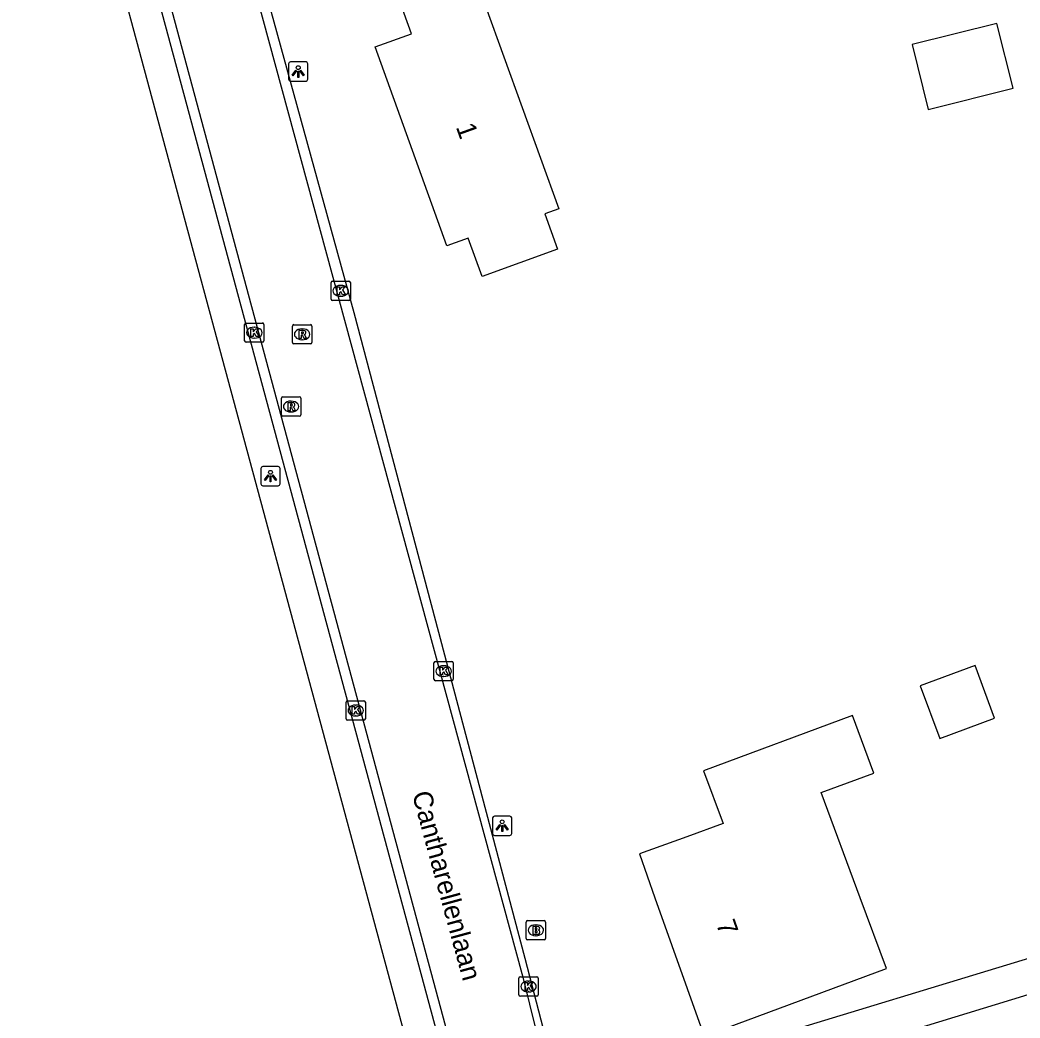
# Model space of a CAD drawing. Extents: x 162675 to 163482, y 379761 to 381227.
# Drawn here: x 162822.9 to 162874.7, y 380743.8 to 380795.5 of the extents above; entities that cross this region are included whole.
import ezdxf

# ---------------------------------------------------------------- set-up
doc = ezdxf.new("R2010")
doc.units = 0
for name, color, linetype in [('IMGEO_Brandkraan', 7, 'Continuous'), ('IMGEO_Kolk', 7, 'Continuous'), ('IMGEO_Lichtpunt', 7, 'Continuous'), ('IMGEO_Openbare_ruimte_label', 7, 'Continuous'), ('IMGEO_Pand', 7, 'Continuous'), ('IMGEO_Pand_nummerreeks', 7, 'Continuous'), ('IMGEO_Rijbaan_lokaal_gesloten', 7, 'Continuous'), ('IMGEO_Rijbaan_lokaal_open', 7, 'Continuous'), ('IMGEO_Rioolput', 7, 'Continuous'), ('IMGEO_Voetpad_open', 7, 'Continuous')]:
    doc.layers.add(name, color=color, linetype=linetype)

msp = doc.modelspace()

# ---------------------------------------------------------------- linework, layer by layer
at = {"layer": 'IMGEO_Brandkraan'}
for p, q in [((162849.144, 380747.89), (162849.144, 380748.742)), ((162849.219, 380748.816), (162850.071, 380748.816)), ((162850.145, 380748.742), (162850.145, 380747.89)), ((162849.632, 380748.596), (162849.657, 380748.596)), ((162850.071, 380747.816), (162849.219, 380747.816)), ((162849.655, 380748.036), (162849.63, 380748.036))]:
    msp.add_line(p, q, dxfattribs=at)
for points in [[(162849.144, 380747.89), (162849.144, 380748.742)], [(162849.219, 380748.816), (162850.071, 380748.816)], [(162850.145, 380748.742), (162850.145, 380747.89)], [(162849.492, 380748.516), (162849.492, 380748.116), (162849.705, 380748.116)], [(162849.723, 380748.516), (162849.492, 380748.516)], [(162849.671, 380748.435), (162849.617, 380748.435), (162849.617, 380748.359)], [(162849.617, 380748.359), (162849.67, 380748.359)], [(162849.679, 380748.283), (162849.617, 380748.283), (162849.617, 380748.202)], [(162850.071, 380747.816), (162849.219, 380747.816)], [(162849.617, 380748.202), (162849.679, 380748.202)]]:
    msp.add_lwpolyline(points, dxfattribs=at)
for centre, radius, start, end in [((162849.221, 380748.74), 0.0765, 91.552, 178.448), ((162849.221, 380748.74), 0.0765, 91.552, 178.448), ((162850.069, 380748.74), 0.0765, 1.552, 88.448), ((162850.069, 380748.74), 0.0765, 1.552, 88.448), ((162849.672, 380748.397), 0.0379, 267.8285, 90.9355), ((162849.68, 380748.242), 0.0404, 269.8759, 90.5077), ((162849.727, 380748.371), 0.145, 59.4692, 91.5367), ((162849.752, 380748.418), 0.0922, 285.5137, 58.1501), ((162849.757, 380748.226), 0.105, 301.3115, 78.989), ((162849.221, 380747.892), 0.0765, 181.552, 268.448), ((162849.221, 380747.892), 0.0765, 181.552, 268.448), ((162849.711, 380748.367), 0.251, 268.6676, 293.5347), ((162850.069, 380747.892), 0.0765, 271.552, 358.448), ((162850.069, 380747.892), 0.0765, 271.552, 358.448)]:
    msp.add_arc(centre, radius, start, end, dxfattribs=at)
for centre, major_axis, ratio, start_param, end_param in [((162849.631, 380748.316), (-0.387, 0.002), 0.722429, 4.712389, 7.853982), ((162849.656, 380748.316), (-0.39, 0.002), 0.717154, 1.570796, 4.712389)]:
    msp.add_ellipse(centre, major_axis=major_axis, ratio=ratio, start_param=start_param, end_param=end_param, dxfattribs=at)
at = {"layer": 'IMGEO_Kolk'}
for p, q in [((162839.111, 380781.945), (162839.963, 380781.945)), ((162839.036, 380781.019), (162839.036, 380781.871)), ((162839.524, 380781.725), (162839.549, 380781.725)), ((162840.037, 380781.871), (162840.037, 380781.019)), ((162839.963, 380780.945), (162839.111, 380780.945)), ((162839.547, 380781.165), (162839.522, 380781.165)), ((162834.56, 380778.851), (162834.56, 380779.703)), ((162834.635, 380779.777), (162835.487, 380779.777)), ((162835.048, 380779.557), (162835.073, 380779.557)), ((162835.561, 380779.703), (162835.561, 380778.851)), ((162835.071, 380778.997), (162835.046, 380778.997)), ((162835.487, 380778.777), (162834.635, 380778.777)), ((162844.442, 380762.244), (162845.294, 380762.244)), ((162844.367, 380761.318), (162844.367, 380762.17)), ((162844.855, 380762.024), (162844.88, 380762.024)), ((162845.368, 380762.17), (162845.368, 380761.318)), ((162845.294, 380761.244), (162844.442, 380761.244)), ((162844.878, 380761.464), (162844.853, 380761.464)), ((162839.891, 380760.204), (162840.743, 380760.204)), ((162839.816, 380759.278), (162839.816, 380760.13)), ((162840.304, 380759.984), (162840.329, 380759.984)), ((162840.817, 380760.13), (162840.817, 380759.278)), ((162840.743, 380759.204), (162839.891, 380759.204)), ((162840.327, 380759.424), (162840.302, 380759.424)), ((162848.767, 380744.978), (162848.767, 380745.83)), ((162848.842, 380745.904), (162849.694, 380745.904)), ((162849.255, 380745.684), (162849.28, 380745.684)), ((162849.768, 380745.83), (162849.768, 380744.978)), ((162849.278, 380745.124), (162849.253, 380745.124)), ((162849.694, 380744.904), (162848.842, 380744.904))]:
    msp.add_line(p, q, dxfattribs=at)
for points in [[(162839.111, 380781.945), (162839.963, 380781.945)], [(162839.036, 380781.019), (162839.036, 380781.871)], [(162839.357, 380781.645), (162839.48, 380781.645), (162839.48, 380781.494), (162839.61, 380781.645), (162839.774, 380781.645), (162839.628, 380781.494), (162839.781, 380781.245), (162839.629, 380781.245), (162839.544, 380781.409), (162839.48, 380781.342), (162839.48, 380781.245), (162839.357, 380781.245), (162839.357, 380781.645)], [(162840.037, 380781.871), (162840.037, 380781.019)], [(162839.963, 380780.945), (162839.111, 380780.945)], [(162834.56, 380778.851), (162834.56, 380779.703)], [(162834.635, 380779.777), (162835.487, 380779.777)], [(162834.881, 380779.477), (162835.004, 380779.477), (162835.004, 380779.326), (162835.134, 380779.477), (162835.298, 380779.477), (162835.152, 380779.326), (162835.305, 380779.077), (162835.153, 380779.077), (162835.068, 380779.241), (162835.004, 380779.174), (162835.004, 380779.077), (162834.881, 380779.077), (162834.881, 380779.477)], [(162835.561, 380779.703), (162835.561, 380778.851)], [(162835.487, 380778.777), (162834.635, 380778.777)], [(162844.442, 380762.244), (162845.294, 380762.244)], [(162844.367, 380761.318), (162844.367, 380762.17)], [(162844.688, 380761.944), (162844.811, 380761.944), (162844.811, 380761.793), (162844.941, 380761.944), (162845.105, 380761.944), (162844.959, 380761.793), (162845.112, 380761.544), (162844.96, 380761.544), (162844.875, 380761.708), (162844.811, 380761.641), (162844.811, 380761.544), (162844.688, 380761.544), (162844.688, 380761.944)], [(162845.368, 380762.17), (162845.368, 380761.318)], [(162845.294, 380761.244), (162844.442, 380761.244)], [(162839.891, 380760.204), (162840.743, 380760.204)], [(162839.816, 380759.278), (162839.816, 380760.13)], [(162840.137, 380759.904), (162840.26, 380759.904), (162840.26, 380759.753), (162840.39, 380759.904), (162840.554, 380759.904), (162840.408, 380759.753), (162840.561, 380759.504), (162840.409, 380759.504), (162840.324, 380759.668), (162840.26, 380759.601), (162840.26, 380759.504), (162840.137, 380759.504), (162840.137, 380759.904)], [(162840.817, 380760.13), (162840.817, 380759.278)], [(162840.743, 380759.204), (162839.891, 380759.204)], [(162848.767, 380744.978), (162848.767, 380745.83)], [(162848.842, 380745.904), (162849.694, 380745.904)], [(162849.768, 380745.83), (162849.768, 380744.978)], [(162849.088, 380745.604), (162849.211, 380745.604), (162849.211, 380745.453), (162849.341, 380745.604), (162849.505, 380745.604), (162849.359, 380745.453), (162849.512, 380745.204), (162849.36, 380745.204), (162849.275, 380745.368), (162849.211, 380745.301), (162849.211, 380745.204), (162849.088, 380745.204), (162849.088, 380745.604)], [(162849.694, 380744.904), (162848.842, 380744.904)]]:
    msp.add_lwpolyline(points, dxfattribs=at)
for centre, start, end in [((162839.113, 380781.869), 91.552, 178.448), ((162839.113, 380781.869), 91.552, 178.448), ((162839.961, 380781.869), 1.552, 88.448), ((162839.961, 380781.869), 1.552, 88.448), ((162839.113, 380781.021), 181.552, 268.448), ((162839.113, 380781.021), 181.552, 268.448), ((162839.961, 380781.021), 271.552, 358.448), ((162839.961, 380781.021), 271.552, 358.448), ((162834.637, 380779.701), 91.552, 178.448), ((162834.637, 380779.701), 91.552, 178.448), ((162835.485, 380779.701), 1.552, 88.448), ((162835.485, 380779.701), 1.552, 88.448), ((162834.637, 380778.853), 181.552, 268.448), ((162834.637, 380778.853), 181.552, 268.448), ((162835.485, 380778.853), 271.552, 358.448), ((162835.485, 380778.853), 271.552, 358.448), ((162844.444, 380762.168), 91.552, 178.448), ((162844.444, 380762.168), 91.552, 178.448), ((162845.292, 380762.168), 1.552, 88.448), ((162845.292, 380762.168), 1.552, 88.448), ((162844.444, 380761.32), 181.552, 268.448), ((162844.444, 380761.32), 181.552, 268.448), ((162845.292, 380761.32), 271.552, 358.448), ((162845.292, 380761.32), 271.552, 358.448), ((162839.893, 380760.128), 91.552, 178.448), ((162839.893, 380760.128), 91.552, 178.448), ((162840.741, 380760.128), 1.552, 88.448), ((162840.741, 380760.128), 1.552, 88.448), ((162839.893, 380759.28), 181.552, 268.448), ((162839.893, 380759.28), 181.552, 268.448), ((162840.741, 380759.28), 271.552, 358.448), ((162840.741, 380759.28), 271.552, 358.448), ((162848.844, 380745.828), 91.552, 178.448), ((162848.844, 380745.828), 91.552, 178.448), ((162849.692, 380745.828), 1.552, 88.448), ((162849.692, 380745.828), 1.552, 88.448), ((162848.844, 380744.98), 181.552, 268.448), ((162848.844, 380744.98), 181.552, 268.448), ((162849.692, 380744.98), 271.552, 358.448), ((162849.692, 380744.98), 271.552, 358.448)]:
    msp.add_arc(centre, 0.0765, start, end, dxfattribs=at)
for centre, major_axis, ratio, start_param, end_param in [((162839.523, 380781.445), (-0.387, 0.002), 0.722429, 4.712389, 7.853982), ((162839.548, 380781.445), (-0.39, 0.002), 0.717154, 1.570796, 4.712389), ((162835.047, 380779.277), (-0.387, 0.002), 0.722429, 4.712389, 7.853982), ((162835.072, 380779.277), (-0.39, 0.002), 0.717154, 1.570796, 4.712389), ((162844.854, 380761.744), (-0.387, 0.002), 0.722429, 4.712389, 7.853982), ((162844.879, 380761.744), (-0.39, 0.002), 0.717154, 1.570796, 4.712389), ((162840.303, 380759.704), (-0.387, 0.002), 0.722429, 4.712389, 7.853982), ((162840.328, 380759.704), (-0.39, 0.002), 0.717154, 1.570796, 4.712389), ((162849.254, 380745.404), (-0.387, 0.002), 0.722429, 4.712389, 7.853982), ((162849.279, 380745.404), (-0.39, 0.002), 0.717154, 1.570796, 4.712389)]:
    msp.add_ellipse(centre, major_axis=major_axis, ratio=ratio, start_param=start_param, end_param=end_param, dxfattribs=at)
at = {"layer": 'IMGEO_Lichtpunt'}
for p, q in [((162837.741, 380793.305), (162836.933, 380793.305)), ((162837.741, 380793.305), (162836.933, 380793.305)), ((162836.839, 380793.21), (162836.839, 380792.403)), ((162836.839, 380793.21), (162836.839, 380792.403)), ((162837.835, 380792.403), (162837.835, 380793.21)), ((162837.835, 380792.403), (162837.835, 380793.21)), ((162836.933, 380792.309), (162837.741, 380792.309)), ((162836.933, 380792.309), (162837.741, 380792.309)), ((162835.401, 380772.247), (162835.401, 380771.44)), ((162835.401, 380772.247), (162835.401, 380771.44)), ((162836.303, 380772.342), (162835.495, 380772.342)), ((162836.303, 380772.342), (162835.495, 380772.342)), ((162836.397, 380771.44), (162836.397, 380772.247)), ((162836.397, 380771.44), (162836.397, 380772.247)), ((162835.495, 380771.346), (162836.303, 380771.346)), ((162835.495, 380771.346), (162836.303, 380771.346)), ((162847.404, 380754.134), (162847.404, 380753.327)), ((162847.404, 380754.134), (162847.404, 380753.327)), ((162848.306, 380754.229), (162847.498, 380754.229)), ((162848.306, 380754.229), (162847.498, 380754.229)), ((162848.4, 380753.327), (162848.4, 380754.134)), ((162848.4, 380753.327), (162848.4, 380754.134)), ((162847.498, 380753.233), (162848.306, 380753.233)), ((162847.498, 380753.233), (162848.306, 380753.233))]:
    msp.add_line(p, q, dxfattribs=at)
for points in [[(162837.213, 380792.874), (162837.252, 380792.846), (162837.064, 380792.584), (162837.026, 380792.611), (162837.213, 380792.874)], [(162837.315, 380792.826), (162837.362, 380792.826), (162837.362, 380792.504), (162837.315, 380792.504), (162837.315, 380792.826)], [(162837.425, 380792.846), (162837.463, 380792.873), (162837.65, 380792.611), (162837.611, 380792.583), (162837.425, 380792.846)], [(162835.775, 380771.911), (162835.814, 380771.883), (162835.626, 380771.621), (162835.588, 380771.648), (162835.775, 380771.911)], [(162835.877, 380771.863), (162835.924, 380771.863), (162835.924, 380771.541), (162835.877, 380771.541), (162835.877, 380771.863)], [(162835.987, 380771.883), (162836.025, 380771.91), (162836.212, 380771.648), (162836.173, 380771.62), (162835.987, 380771.883)], [(162847.778, 380753.798), (162847.817, 380753.77), (162847.629, 380753.508), (162847.591, 380753.535), (162847.778, 380753.798)], [(162847.88, 380753.75), (162847.927, 380753.75), (162847.927, 380753.428), (162847.88, 380753.428), (162847.88, 380753.75)], [(162847.99, 380753.77), (162848.028, 380753.797), (162848.215, 380753.535), (162848.176, 380753.507), (162847.99, 380753.77)]]:
    msp.add_lwpolyline(points, dxfattribs=at)
for centre in [(162837.338, 380793.008), (162835.9, 380772.045), (162847.903, 380753.932)]:
    msp.add_circle(centre, 0.0994, dxfattribs=at)
for centre, start, end in [((162836.933, 380793.21), 90, 180), ((162836.933, 380793.21), 90, 180), ((162837.741, 380793.21), 0, 90), ((162837.741, 380793.21), 0, 90), ((162836.933, 380792.403), 180, 270), ((162836.933, 380792.403), 180, 270), ((162837.741, 380792.403), 270, 0), ((162837.741, 380792.403), 270, 360), ((162835.495, 380772.247), 90, 180), ((162835.495, 380772.247), 90, 180), ((162836.303, 380772.247), 0, 90), ((162836.303, 380772.247), 0, 90), ((162835.495, 380771.44), 180, 270), ((162835.495, 380771.44), 180, 270), ((162836.303, 380771.44), 270, 0), ((162836.303, 380771.44), 270, 360), ((162847.498, 380754.134), 90, 180), ((162847.498, 380754.134), 90, 180), ((162848.306, 380754.134), 0, 90), ((162848.306, 380754.134), 0, 90), ((162847.498, 380753.327), 180, 270), ((162847.498, 380753.327), 180, 270), ((162848.306, 380753.327), 270, 0), ((162848.306, 380753.327), 270, 360)]:
    msp.add_arc(centre, 0.0946, start, end, dxfattribs=at)
at = {"layer": 'IMGEO_Pand'}
for points in [[(162846.863, 380782.19), (162846.147, 380784.174), (162845.036, 380783.773), (162841.318, 380794.083), (162843.205, 380794.764), (162840.427, 380802.469), (162846.288, 380804.582), (162847.922, 380800.05), (162849.683, 380800.685), (162850.815, 380797.547), (162847.046, 380796.188), (162850.829, 380785.694), (162850.111, 380785.436), (162850.772, 380783.603), (162846.863, 380782.19)], [(162869.135, 380794.205), (162869.974, 380790.841), (162874.369, 380791.938), (162873.529, 380795.301), (162869.135, 380794.205)], [(162869.558, 380760.984), (162870.568, 380758.259), (162873.403, 380759.311), (162872.393, 380762.035), (162869.558, 380760.984)], [(162857.472, 380753.166), (162855.006, 380752.271), (162855.815, 380750), (162858.368, 380742.833), (162867.809, 380746.333), (162866.449, 380750), (162864.43, 380755.447), (162867.159, 380756.459), (162866.05, 380759.45), (162858.324, 380756.585), (162859.341, 380753.844), (162857.472, 380753.166)]]:
    msp.add_lwpolyline(points, dxfattribs=at)
at = {"layer": 'IMGEO_Rijbaan_lokaal_gesloten'}
for points in [[(162828.98, 380819.787), (162834.489, 380799.29), (162848.978, 380745.879), (162849.986, 380741.76), (162850.036, 380741.572)], [(162845.757, 380740.437), (162825, 380817.481)]]:
    msp.add_lwpolyline(points, dxfattribs=at)
at = {"layer": 'IMGEO_Rijbaan_lokaal_open'}
for points in [[(162851.047, 380739.531), (162850.394, 380741.856), (162849.091, 380746.861), (162840.23, 380780.296), (162835.049, 380799.153), (162834.599, 380800.825), (162829.461, 380819.913)], [(162847.761, 380730.994), (162847.206, 380733.053), (162824.53, 380817.239)]]:
    msp.add_lwpolyline(points, dxfattribs=at)
at = {"layer": 'IMGEO_Rioolput'}
for p, q in [((162837.039, 380778.765), (162837.039, 380779.617)), ((162837.114, 380779.691), (162837.966, 380779.691)), ((162837.527, 380779.471), (162837.552, 380779.471)), ((162838.04, 380779.617), (162838.04, 380778.765)), ((162837.55, 380778.911), (162837.525, 380778.911)), ((162837.966, 380778.691), (162837.114, 380778.691)), ((162836.467, 380775.023), (162836.467, 380775.875)), ((162836.542, 380775.949), (162837.394, 380775.949)), ((162836.955, 380775.729), (162836.98, 380775.729)), ((162837.468, 380775.875), (162837.468, 380775.023)), ((162836.978, 380775.169), (162836.953, 380775.169)), ((162837.394, 380774.949), (162836.542, 380774.949))]:
    msp.add_line(p, q, dxfattribs=at)
for points in [[(162837.039, 380778.765), (162837.039, 380779.617)], [(162837.114, 380779.691), (162837.966, 380779.691)], [(162837.628, 380779.389), (162837.376, 380779.391), (162837.376, 380778.991)], [(162837.554, 380779.31), (162837.5, 380779.31), (162837.5, 380779.229)], [(162838.04, 380779.617), (162838.04, 380778.765)], [(162837.376, 380778.991), (162837.5, 380778.991), (162837.5, 380779.153), (162837.511, 380779.153)], [(162837.5, 380779.229), (162837.552, 380779.229)], [(162837.558, 380779.124), (162837.629, 380778.991), (162837.769, 380778.991), (162837.704, 380779.117)], [(162837.966, 380778.691), (162837.114, 380778.691)], [(162836.467, 380775.023), (162836.467, 380775.875)], [(162836.542, 380775.949), (162837.394, 380775.949)], [(162837.468, 380775.875), (162837.468, 380775.023)], [(162837.056, 380775.647), (162836.804, 380775.649), (162836.804, 380775.249)], [(162836.804, 380775.249), (162836.928, 380775.249), (162836.928, 380775.411), (162836.939, 380775.411)], [(162836.982, 380775.568), (162836.928, 380775.568), (162836.928, 380775.487)], [(162836.928, 380775.487), (162836.98, 380775.487)], [(162836.986, 380775.382), (162837.057, 380775.249), (162837.197, 380775.249), (162837.132, 380775.375)], [(162837.394, 380774.949), (162836.542, 380774.949)]]:
    msp.add_lwpolyline(points, dxfattribs=at)
for centre, radius, start, end in [((162837.116, 380779.615), 0.0765, 91.552, 178.448), ((162837.116, 380779.615), 0.0765, 91.552, 178.448), ((162837.56, 380779.214), 0.0964, 77.0061, 93.1865), ((162837.574, 380779.271), 0.0378, 276.6634, 79.6772), ((162837.627, 380779.279), 0.109, 350.3612, 89.416), ((162837.964, 380779.615), 0.0765, 1.552, 88.448), ((162837.964, 380779.615), 0.0765, 1.552, 88.448), ((162837.51, 380779.1), 0.0533, 26.0293, 88.6989), ((162837.536, 380779.418), 0.19, 274.7715, 282.9687), ((162837.625, 380779.279), 0.112, 277.5842, 350.9817), ((162837.609, 380779.064), 0.108, 29.5134, 73.7905), ((162837.116, 380778.767), 0.0765, 181.552, 268.448), ((162837.116, 380778.767), 0.0765, 181.552, 268.448), ((162837.964, 380778.767), 0.0765, 271.552, 358.448), ((162837.964, 380778.767), 0.0765, 271.552, 358.448), ((162836.544, 380775.873), 0.0765, 91.552, 178.448), ((162836.544, 380775.873), 0.0765, 91.552, 178.448), ((162837.392, 380775.873), 0.0765, 1.552, 88.448), ((162837.392, 380775.873), 0.0765, 1.552, 88.448), ((162836.938, 380775.358), 0.0533, 26.0293, 88.6989), ((162836.964, 380775.676), 0.19, 274.7715, 282.9687), ((162836.988, 380775.472), 0.0964, 77.0061, 93.1865), ((162837.002, 380775.529), 0.0378, 276.6634, 79.6772), ((162837.055, 380775.537), 0.109, 350.3612, 89.416), ((162837.053, 380775.537), 0.112, 277.5842, 350.9817), ((162837.037, 380775.322), 0.108, 29.5134, 73.7905), ((162836.544, 380775.025), 0.0765, 181.552, 268.448), ((162836.544, 380775.025), 0.0765, 181.552, 268.448), ((162837.392, 380775.025), 0.0765, 271.552, 358.448), ((162837.392, 380775.025), 0.0765, 271.552, 358.448)]:
    msp.add_arc(centre, radius, start, end, dxfattribs=at)
for centre, major_axis, ratio, start_param, end_param in [((162837.526, 380779.191), (-0.387, 0.002), 0.722429, 4.712389, 7.853982), ((162837.551, 380779.191), (-0.39, 0.002), 0.717154, 1.570796, 4.712389), ((162836.954, 380775.449), (-0.387, 0.002), 0.722429, 4.712389, 7.853982), ((162836.979, 380775.449), (-0.39, 0.002), 0.717154, 1.570796, 4.712389)]:
    msp.add_ellipse(centre, major_axis=major_axis, ratio=ratio, start_param=start_param, end_param=end_param, dxfattribs=at)
at = {"layer": 'IMGEO_Voetpad_open'}
for points in [[(162822.925, 380816.802), (162845.6, 380732.652)], [(162851.047, 380739.531), (162885.452, 380750), (162905.036, 380755.959), (162905.139, 380755.989)], [(162851.835, 380737.865), (162891.515, 380750), (162905.14, 380754.167), (162905.631, 380754.311)]]:
    msp.add_lwpolyline(points, dxfattribs=at)

# ---------------------------------------------------------------- texts
at = {"layer": 'IMGEO_Openbare_ruimte_label'}
msp.add_text('Cantharellenlaan', height=1, rotation=285.2451, dxfattribs=at).set_placement((162843.224, 380755.383))
at = {"layer": 'IMGEO_Pand_nummerreeks'}
for s, rotation, p in [('1', 289.8304, (162845.493, 380789.935)), ('7', 289.6069, (162858.968, 380748.657))]:
    msp.add_text(s, height=1, rotation=rotation, dxfattribs=at).set_placement(p)

doc.saveas('drawing.dxf')
